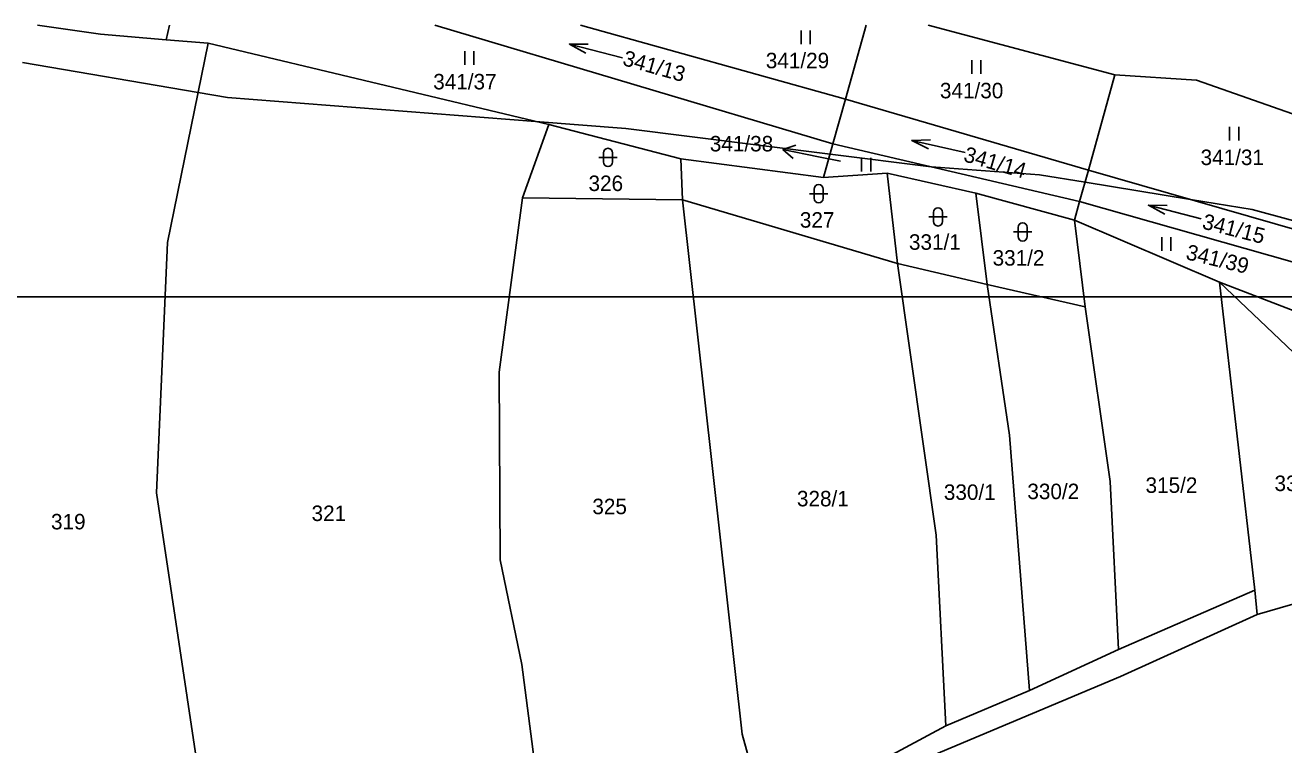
# Model space of a CAD drawing. Extents: x -756640 to -756220, y -1116060 to -1115741.
# Drawn here: x -756499.3 to -756361.1, y -1115820.2 to -1115741.2 of the extents above; entities that cross this region are included whole.
import ezdxf

# ---------------------------------------------------------------- set-up
doc = ezdxf.new("R2010")
doc.units = 0
for name, color, linetype in [('BPEJ', 7, 'Continuous'), ('Katastr_HRANICE DRÁHY', 7, 'Continuous'), ('Katastr_Hranice parcel', 7, 'Continuous'), ('Katastr_Parcelní čísla', 7, 'Continuous'), ('Katastr_Značky kultur', 7, 'Continuous')]:
    doc.layers.add(name, color=color, linetype=linetype)

msp = doc.modelspace()

# ---------------------------------------------------------------- linework, layer by layer
at = {"layer": 'BPEJ'}
msp.add_lwpolyline([(-756499.55, -1115745.29), (-756480.27, -1115748.57), (-756477.06, -1115749.11), (-756443.26, -1115751.74), (-756433.35, -1115752.51), (-756410.94, -1115755.34), (-756399.83, -1115756.75), (-756399.8, -1115756.75), (-756387.95, -1115757.6), (-756382.96, -1115758.42), (-756371.38, -1115760.31), (-756364.61, -1115761.42), (-756355.88, -1115763.78)], dxfattribs=at)
at = {"layer": 'Defpoints'}
msp.add_line((-756640.13, -1115771.02), (-756220.13, -1115771.02), dxfattribs=at)
at = {"layer": 'Katastr_HRANICE DRÁHY'}
for points in [[(-756349.55, -1115801.67), (-756364.06, -1115805.89)], [(-756364.06, -1115805.89), (-756379.08, -1115812.68)], [(-756379.08, -1115812.68), (-756400.89, -1115821.88)]]:
    msp.add_lwpolyline(points, dxfattribs=at)
at = {"layer": 'Katastr_Hranice parcel'}
for points in [[(-756491, -1115742.18), (-756497.89, -1115741.18)], [(-756483.77, -1115742.78), (-756491, -1115742.18)], [(-756483.42, -1115741.18), (-756483.77, -1115742.78)], [(-756410.63, -1115754.22), (-756454.3, -1115741.18)], [(-756438.33, -1115741.18), (-756409.26, -1115749.32)], [(-756406.99, -1115741.18), (-756409.26, -1115749.32)], [(-756400.17, -1115741.18), (-756379.7, -1115746.62)], [(-756479.17, -1115743.17), (-756483.77, -1115742.78)], [(-756479.17, -1115743.17), (-756483.65, -1115765.05)], [(-756479.17, -1115743.17), (-756441.78, -1115752.09)], [(-756379.7, -1115746.62), (-756382.59, -1115757.09)], [(-756379.7, -1115746.62), (-756370.72, -1115747.22)], [(-756370.72, -1115747.22), (-756351.86, -1115753.85)], [(-756409.26, -1115749.32), (-756410.63, -1115754.22)], [(-756409.26, -1115749.32), (-756382.59, -1115757.09)], [(-756441.78, -1115752.09), (-756444.69, -1115760.15)], [(-756427.31, -1115755.86), (-756441.78, -1115752.09)], [(-756410.63, -1115754.22), (-756411.66, -1115757.9)], [(-756383.55, -1115760.55), (-756410.63, -1115754.22)], [(-756427.12, -1115760.35), (-756427.31, -1115755.86)], [(-756427.31, -1115755.86), (-756411.66, -1115757.9)], [(-756411.66, -1115757.9), (-756404.66, -1115757.44)], [(-756404.66, -1115757.44), (-756394.95, -1115759.62)], [(-756404.66, -1115757.44), (-756403.54, -1115767.35)], [(-756382.59, -1115757.09), (-756383.55, -1115760.55)], [(-756382.59, -1115757.09), (-756356.23, -1115764.66)], [(-756444.69, -1115760.15), (-756447.25, -1115779.26)], [(-756444.69, -1115760.15), (-756427.12, -1115760.35)], [(-756394.95, -1115759.62), (-756384.11, -1115762.59)], [(-756393.69, -1115769.66), (-756394.95, -1115759.62)], [(-756403.54, -1115767.35), (-756427.12, -1115760.35)], [(-756427.12, -1115760.35), (-756420.59, -1115819.01)], [(-756383.55, -1115760.55), (-756384.11, -1115762.59)], [(-756357.53, -1115767.92), (-756383.55, -1115760.55)], [(-756384.11, -1115762.59), (-756382.93, -1115772.11)], [(-756384.11, -1115762.59), (-756368.19, -1115769.4)], [(-756483.65, -1115765.05), (-756484.84, -1115792.54)], [(-756403.54, -1115767.35), (-756393.69, -1115769.66)], [(-756403.54, -1115767.35), (-756399.29, -1115797.17)], [(-756382.93, -1115772.11), (-756393.69, -1115769.66)], [(-756393.69, -1115769.66), (-756391.23, -1115786.2)], [(-756368.19, -1115769.4), (-756358.61, -1115778.51)], [(-756368.19, -1115769.4), (-756359.47, -1115772.77)], [(-756368.19, -1115769.4), (-756364.32, -1115803.23)], [(-756382.93, -1115772.11), (-756380.19, -1115791.29)], [(-756447.25, -1115779.26), (-756447.12, -1115799.88)], [(-756391.23, -1115786.2), (-756389.05, -1115814.22)], [(-756380.19, -1115791.29), (-756379.27, -1115809.72)], [(-756484.84, -1115792.54), (-756476.32, -1115849.42)], [(-756399.29, -1115797.17), (-756398.23, -1115818.12)], [(-756447.12, -1115799.88), (-756444.74, -1115811.37)], [(-756379.27, -1115809.72), (-756364.32, -1115803.23)], [(-756364.32, -1115803.23), (-756364.06, -1115805.89)], [(-756389.05, -1115814.22), (-756379.27, -1115809.72)], [(-756444.74, -1115811.37), (-756443.42, -1115821.82)], [(-756398.23, -1115818.12), (-756389.05, -1115814.22)], [(-756417.92, -1115828.69), (-756398.23, -1115818.12)], [(-756420.59, -1115819.01), (-756417.92, -1115828.69)]]:
    msp.add_lwpolyline(points, dxfattribs=at)
at = {"layer": 'Katastr_Parcelní čísla'}
for p, q in [((-756414.99, -1115755.83), (-756416.11, -1115754.84)), ((-756409.79, -1115756.12), (-756412.19, -1115755.63))]:
    msp.add_line(p, q, dxfattribs=at)
msp.add_lwpolyline([(-756412.19, -1115755.63), (-756416.11, -1115754.84), (-756414.69, -1115754.36)], dxfattribs=at)
at = {"layer": 'Katastr_Značky kultur'}
for p, q in [((-756414.11, -1115741.75), (-756414.11, -1115743.25)), ((-756413.11, -1115743.25), (-756413.11, -1115741.75)), ((-756433.73, -1115744.78), (-756439.53, -1115743.25)), ((-756451.03, -1115744.04), (-756451.03, -1115745.54)), ((-756450.03, -1115745.54), (-756450.03, -1115744.04)), ((-756395.38, -1115745.01), (-756395.38, -1115746.51)), ((-756394.38, -1115746.51), (-756394.38, -1115745.01)), ((-756367.1, -1115752.34), (-756367.1, -1115753.84)), ((-756366.1, -1115753.84), (-756366.1, -1115752.34)), ((-756396.11, -1115755.15), (-756401.97, -1115753.83)), ((-756436.31, -1115755.7), (-756434.31, -1115755.7)), ((-756435.81, -1115755.2), (-756435.81, -1115756.2)), ((-756434.81, -1115755.2), (-756434.81, -1115756.2)), ((-756407.47, -1115755.74), (-756407.47, -1115757.24)), ((-756406.47, -1115757.24), (-756406.47, -1115755.74)), ((-756413.19, -1115759.68), (-756411.19, -1115759.68)), ((-756412.69, -1115759.18), (-756412.69, -1115760.18)), ((-756411.69, -1115759.18), (-756411.69, -1115760.18)), ((-756370.2, -1115762.45), (-756376, -1115760.95)), ((-756400.09, -1115762.23), (-756398.09, -1115762.23)), ((-756399.59, -1115761.73), (-756399.59, -1115762.73)), ((-756398.59, -1115761.73), (-756398.59, -1115762.73)), ((-756390.81, -1115763.88), (-756388.81, -1115763.88)), ((-756390.31, -1115763.38), (-756390.31, -1115764.38)), ((-756389.31, -1115763.38), (-756389.31, -1115764.38)), ((-756374.53, -1115764.44), (-756374.53, -1115765.94)), ((-756373.53, -1115765.94), (-756373.53, -1115764.44))]:
    msp.add_line(p, q, dxfattribs=at)
for points in [[(-756437.73, -1115744.24), (-756439.53, -1115743.25), (-756437.47, -1115743.27)], [(-756400.13, -1115754.76), (-756401.97, -1115753.83), (-756399.91, -1115753.78)], [(-756374.19, -1115761.93), (-756376, -1115760.95), (-756373.94, -1115760.97)]]:
    msp.add_lwpolyline(points, dxfattribs=at)
for centre, start, end in [((-756435.31, -1115755.2), 0, 180), ((-756435.31, -1115756.2), 180, 0), ((-756412.19, -1115759.18), 0, 180), ((-756412.19, -1115760.18), 180, 0), ((-756399.09, -1115761.73), 0, 180), ((-756399.09, -1115762.73), 180, 0), ((-756389.81, -1115763.38), 0, 180), ((-756389.81, -1115764.38), 180, 0)]:
    msp.add_arc(centre, 0.5, start, end, dxfattribs=at)

# ---------------------------------------------------------------- texts
at = {"layer": 'Katastr_Parcelní čísla'}
for s, rotation, p in [('341/13', 344.1959, (-756433.8, -1115745.54)), ('341/14', 343.9074, (-756396.39, -1115756.1)), ('341/15', 345.681, (-756370.21, -1115763.49)), ('341/39', 346.4088, (-756371.99, -1115766.86))]:
    msp.add_text(s, height=1.7, rotation=rotation, dxfattribs=at).set_placement(p)
for s, p in [('341/29', (-756417.99, -1115745.91)), ('341/37', (-756454.48, -1115748.23)), ('341/30', (-756398.88, -1115749.21)), ('341/38', (-756424.13, -1115755.04)), ('341/31', (-756370.28, -1115756.54)), ('326', (-756437.44, -1115759.39)), ('327', (-756414.25, -1115763.41)), ('331/1', (-756402.28, -1115765.84)), ('331/2', (-756393.1, -1115767.58)), ('333/1', (-756362.17, -1115792.33)), ('330/1', (-756398.45, -1115793.3)), ('330/2', (-756389.29, -1115793.22)), ('315/2', (-756376.32, -1115792.53)), ('325', (-756437.02, -1115794.87)), ('328/1', (-756414.57, -1115794.01)), ('321', (-756467.83, -1115795.62)), ('319', (-756496.42, -1115796.54))]:
    msp.add_text(s, height=1.7, dxfattribs=at).set_placement(p)

doc.saveas('drawing.dxf')
